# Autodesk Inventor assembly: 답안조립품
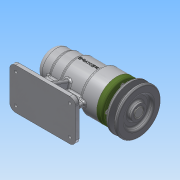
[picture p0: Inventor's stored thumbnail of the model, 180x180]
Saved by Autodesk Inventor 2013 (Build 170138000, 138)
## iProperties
Created: 2016-06
Part Number: 답안조립품
Document SubType Name: Assembly
Designer: Administrator
Author: Administrator
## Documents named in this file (12)
- C:\Users\Administrator\Desktop\460608V1022\답안조립품.iam
- C:\Users\Administrator\Desktop\460608V1022\본체.ipt
- C:\Users\Administrator\Desktop\460608V1022\V벨트풀리.ipt
- C:\Users\Administrator\Desktop\460608V1022\멈춤나사 M3x8.ipt
- C:\Users\Administrator\Desktop\460608V1022\베어링 6004.ipt
- C:\Users\Administrator\Desktop\460608V1022\베어링 51202.ipt
- C:\Users\Administrator\Desktop\460608V1022\볼트 M4 x 12.ipt
- C:\Users\Administrator\Desktop\460608V1022\어댑터슬리브.ipt
- C:\Users\Administrator\Desktop\460608V1022\오일 실.ipt
- C:\Users\Administrator\Desktop\460608V1022\축.ipt
- C:\Users\Administrator\Desktop\460608V1022\커버.ipt
- C:\Users\Administrator\Desktop\460608V1022\키 5 x 5 x 16.ipt
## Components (6 placed, 2 different names)
1. V벨트풀리:1
2. ISO 4762 M4 x 12:1
3. ISO 4762 M4 x 12:2
4. ISO 4762 M4 x 12:3
5. ISO 4762 M4 x 12:4
6. ISO 4762 M4 x 12:5
